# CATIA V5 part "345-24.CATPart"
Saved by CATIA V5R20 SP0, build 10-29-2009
Part number: 345-24
Definition: NONE
Nomenclature: 345-24
Source: Unknown
Description: 345-24
Bounding box of the stored display mesh (mm): x 0 to 63, y -31.5 to 31.5, z -31.5 to 31.5
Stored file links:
  C:\Users\Utente\Desktop\IO LAVORO\3D X SITO CF\X SITO\345-346\345-24.CATPart
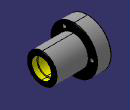
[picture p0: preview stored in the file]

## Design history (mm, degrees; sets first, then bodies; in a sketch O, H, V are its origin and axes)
Body1 "345-24" (main body)
  Solid1: solid without history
